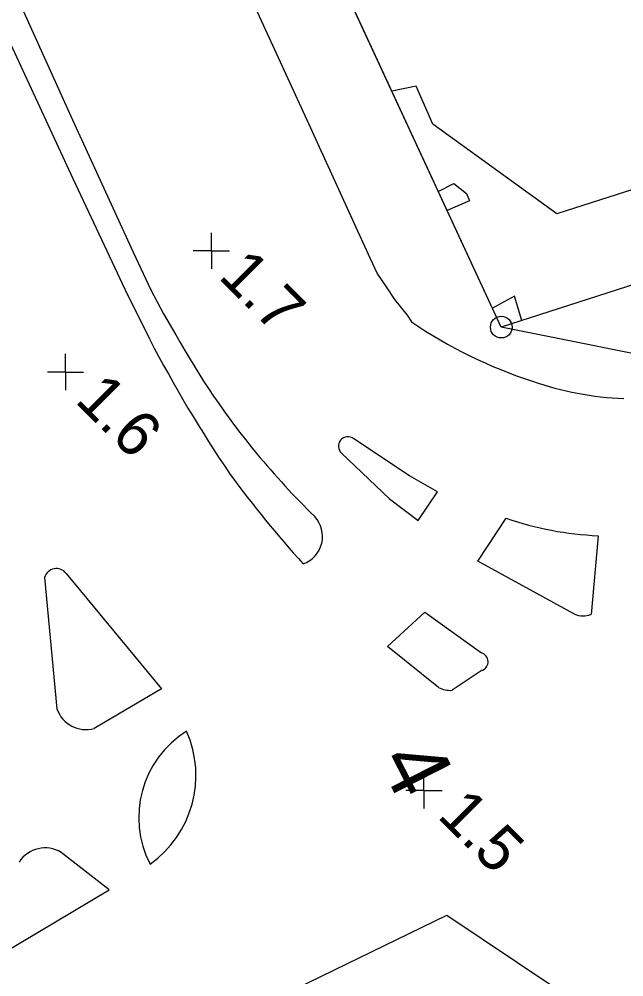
# Model space of a CAD drawing. Extents: x 1596643 to 1597288, y 13057194 to 13057957.
# Drawn here: x 1596999.4 to 1597032.9, y 13057462.8 to 13057515.8 of the extents above; entities that cross this region are included whole.
import ezdxf

# ---------------------------------------------------------------- set-up
doc = ezdxf.new("R2010")
doc.units = 0
for name, color, linetype in [('BAS byggnad anläggning L', 7, 'Continuous'), ('BAS gränspunkt P', 7, 'Continuous'), ('BAS Level 16', 7, 'Continuous'), ('BAS Level 36', 7, 'Continuous'), ('BAS Level 37', 7, 'Continuous'), ('BAS markytetext T', 7, 'Continuous'), ('BAS vägbanekant L', 7, 'Continuous'), ('BAS vägbanekant skymd L', 7, 'Continuous')]:
    doc.layers.add(name, color=color, linetype=linetype)

msp = doc.modelspace()

# ---------------------------------------------------------------- linework, layer by layer
at = {"layer": 'BAS byggnad anläggning L'}
for points in [[(1597026.094, 13057498.758), (1597004.68, 13057545.021)], [(1597082.099, 13057516.804), (1597026.094, 13057498.758)], [(1597027.231, 13057499.124), (1597026.835, 13057500.477), (1597025.607, 13057499.81)]]:
    msp.add_lwpolyline(points, dxfattribs=at)
at = {"layer": 'BAS gränspunkt P'}
for centre, radius in [((1597026.1, 13057498.765), 0.6), ((1597026.1, 13057498.765), 0.6), ((1597026.095, 13057498.758), 0.001), ((1597026.095, 13057498.758), 0.001)]:
    msp.add_circle(centre, radius, dxfattribs=at)
at = {"layer": 'BAS Level 16'}
for p, q in [((1597010.07, 13057502.984), (1597010.07, 13057503.984)), ((1597010.07, 13057502.984), (1597010.07, 13057503.984)), ((1597010.07, 13057502.984), (1597009.07, 13057502.984)), ((1597010.07, 13057502.984), (1597009.07, 13057502.984)), ((1597010.07, 13057502.984), (1597011.07, 13057502.984)), ((1597010.07, 13057502.984), (1597010.07, 13057501.984)), ((1597010.07, 13057502.984), (1597011.07, 13057502.984)), ((1597010.07, 13057502.984), (1597010.07, 13057501.984)), ((1597002.008, 13057496.283), (1597002.008, 13057497.283)), ((1597002.008, 13057496.283), (1597002.008, 13057497.283)), ((1597002.008, 13057496.283), (1597001.008, 13057496.283)), ((1597002.008, 13057496.283), (1597001.008, 13057496.283)), ((1597002.008, 13057496.283), (1597003.008, 13057496.283)), ((1597002.008, 13057496.283), (1597002.008, 13057495.283)), ((1597002.008, 13057496.283), (1597003.008, 13057496.283)), ((1597002.008, 13057496.283), (1597002.008, 13057495.283)), ((1597021.822, 13057473.127), (1597021.822, 13057474.127)), ((1597021.822, 13057473.127), (1597021.822, 13057474.127)), ((1597021.822, 13057473.127), (1597020.822, 13057473.127)), ((1597021.822, 13057473.127), (1597020.822, 13057473.127)), ((1597021.822, 13057473.127), (1597022.822, 13057473.127)), ((1597021.822, 13057473.127), (1597021.822, 13057472.127)), ((1597021.822, 13057473.127), (1597022.822, 13057473.127)), ((1597021.822, 13057473.127), (1597021.822, 13057472.127))]:
    msp.add_line(p, q, dxfattribs=at)
at = {"layer": 'BAS Level 37'}
for points in [[(1597026.094, 13057498.758), (1596996.9, 13057561.829)], [(1597036.945, 13057496.581), (1597026.094, 13057498.758)]]:
    msp.add_lwpolyline(points, dxfattribs=at)
at = {"layer": 'BAS vägbanekant L'}
for points in [[(1596996.636, 13057546.341), (1596997.569, 13057544.703), (1596998.279, 13057543.595), (1597000.409, 13057540.798), (1597001.424, 13057539.364), (1597002.651, 13057537.614), (1597006.3, 13057529.816), (1597011.144, 13057519.404), (1597015.542, 13057509.796), (1597018.826, 13057502.607), (1597019.262, 13057501.703), (1597019.738, 13057500.991), (1597020.195, 13057500.299), (1597020.895, 13057499.424), (1597021.128, 13057499.058)], [(1596988.406, 13057540.327), (1596997.757, 13057520.447), (1597002.399, 13057510.239), (1597005.743, 13057502.909), (1597006.726, 13057500.824), (1597007.415, 13057499.502), (1597008.105, 13057498.343)], [(1596987.288, 13057539.384), (1596991.793, 13057529.926), (1596998.239, 13057515.955), (1597002.404, 13057506.998), (1597005.424, 13057500.562), (1597006.661, 13057498.091)], [(1597017.265, 13057491.787), (1597019.925, 13057489.264), (1597021.509, 13057488.063), (1597022.579, 13057489.657), (1597021.025, 13057490.533), (1597017.937, 13057492.589)], [(1597030.153, 13057482.89), (1597024.8, 13057485.823), (1597026.369, 13057488.199)], [(1597031.45, 13057487.227), (1597031.058, 13057482.868)], [(1597000.848, 13057484.908), (1597001.528, 13057477.642)], [(1597002.037, 13057485.141), (1597007.304, 13057478.752), (1597003.59, 13057476.562)], [(1597019.812, 13057481.104), (1597021.878, 13057483.002), (1597025.006, 13057480.742)], [(1597022.624, 13057478.835), (1597019.812, 13057481.104)], [(1597025.045, 13057479.777), (1597023.376, 13057478.671)], [(1596996.556, 13057462.955), (1597004.421, 13057467.639), (1597001.761, 13057469.705)], [(1597014.75, 13057462.163), (1597023.084, 13057466.234), (1597028.95, 13057462.292)]]:
    msp.add_lwpolyline(points, dxfattribs=at)
for centre, radius, start, end in [((1597035.962, 13057520.857), 26.367, 235.7651, 252.0385), ((1597046.599, 13057519.703), 44.023, 209.0255, 219.3956), ((1597071.566, 13057531.687), 73.085, 207.3669, 214.19169), ((1597033.463, 13057511.71), 16.901, 250.5348, 267.9995), ((1597017.617, 13057492.175), 0.524, 52.2979, 227.7852), ((1597048.658, 13057521.804), 46.948, 219.7823, 225.5601), ((1597059.598, 13057526.023), 60.037, 216.13943, 222.24159), ((1597014.592, 13057487.185), 1.622, 290.1882, 42.6016), ((1597032.151, 13057504.664), 17.451, 250.6503, 267.6978), ((1597001.499, 13057484.733), 0.674, 37.1077, 164.9536), ((1597030.631, 13057483.956), 1.168, 245.8483, 291.3825), ((1597024.858, 13057480.252), 0.512, 291.4888, 73.1935), ((1597023.285, 13057480.062), 1.394, 241.6881, 273.743), ((1597003.133, 13057478.198), 1.699, 199.107, 285.6072), ((1597011.684, 13057471.632), 5.631, 122.0841, 207.3022), ((1597003.211, 13057473.951), 6.005, 305.2859, 24.0981), ((1597000.877, 13057468.246), 1.706, 58.7886, 147.2224)]:
    msp.add_arc(centre, radius, start, end, dxfattribs=at)
at = {"layer": 'BAS vägbanekant skymd L'}
for points in [[(1597105.751, 13057529.705), (1597081.743, 13057521.956), (1597079.065, 13057525.364), (1597078.599, 13057526.391), (1597077.815, 13057526.04), (1597078.293, 13057525.027), (1597077.722, 13057524.787), (1597076.046, 13057520.094), (1597029.16, 13057505.043), (1597022.305, 13057510.001), (1597021.384, 13057512.106), (1597020.048, 13057511.821)], [(1597022.616, 13057506.272), (1597023.479, 13057506.707), (1597024.169, 13057506.168), (1597024.342, 13057505.761), (1597023.105, 13057505.216)]]:
    msp.add_lwpolyline(points, dxfattribs=at)

# ---------------------------------------------------------------- texts
at = {"layer": 'BAS Level 36'}
msp.add_text('4', height=3.5, rotation=296.9611, dxfattribs=at).set_placement((1597019.271, 13057474.773))
at = {"layer": 'BAS markytetext T'}
for s, p in [('1.7', (1597010.392, 13057501.524)), ('1.6', (1597002.474, 13057494.653)), ('1.5', (1597022.502, 13057471.668))]:
    msp.add_text(s, height=2.5, rotation=315, dxfattribs=at).set_placement(p)

doc.saveas('drawing.dxf')
